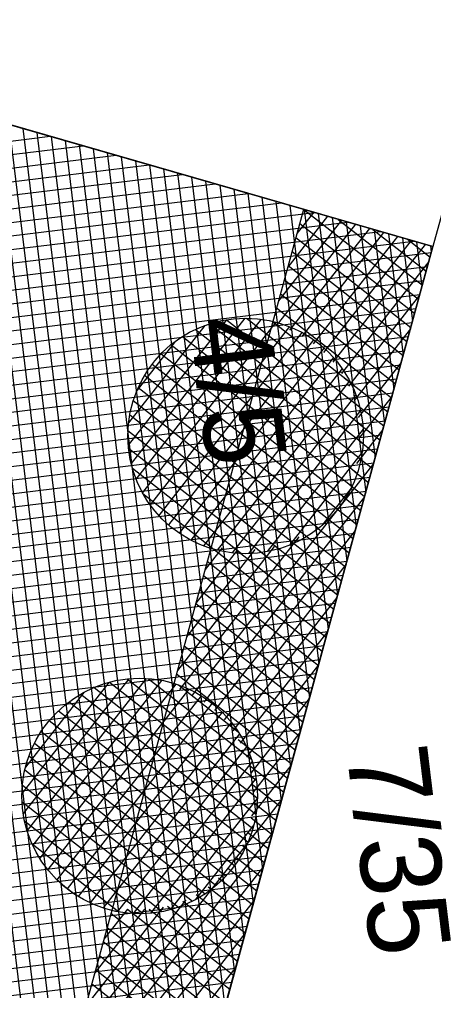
# Model space of a CAD drawing. Extents: x -566982 to -566809, y -1095912 to -1095685.
# Drawn here: x -566840.29 to -566834.14, y -1095771.74 to -1095757.31 of the extents above; entities that cross this region are included whole.
import ezdxf

# ---------------------------------------------------------------- set-up
doc = ezdxf.new("R2010")
doc.units = 0
for name, color, linetype in [('Vrstva 1', 7, 'Continuous'), ('Vrstva 40', 7, 'Continuous'), ('Vrstva 41', 7, 'Continuous'), ('Vrstva 42', 7, 'Continuous'), ('Vrstva 43', 7, 'Continuous'), ('Vrstva 44', 7, 'Continuous')]:
    doc.layers.add(name, color=color, linetype=linetype)

msp = doc.modelspace()

# ---------------------------------------------------------------- linework, layer by layer
at = {"layer": 'Vrstva 1'}
for p, q in [((-566831.34, -1095750.42), (-566834.15, -1095760.69)), ((-566843.76, -1095757.92), (-566834.15, -1095760.69)), ((-566834.15, -1095760.69), (-566839.47, -1095780.13))]:
    msp.add_line(p, q, dxfattribs=at)
at = {"layer": 'Vrstva 41'}
for p, q in [((-566835.922, -1095760.179), (-566836.171, -1095760.496)), ((-566836.07, -1095760.136), (-566834.364, -1095761.472)), ((-566835.508, -1095760.299), (-566836.444, -1095761.494)), ((-566835.715, -1095760.239), (-566836.307, -1095760.995)), ((-566835.556, -1095760.285), (-566834.307, -1095761.263)), ((-566835.301, -1095760.358), (-566836.48, -1095761.865)), ((-566835.094, -1095760.418), (-566836.279, -1095761.933)), ((-566836.129, -1095760.344), (-566834.421, -1095761.681)), ((-566835.043, -1095760.433), (-566834.249, -1095761.053)), ((-566836.186, -1095760.554), (-566834.478, -1095761.89)), ((-566834.886, -1095760.478), (-566836.096, -1095762.023)), ((-566834.679, -1095760.537), (-566835.928, -1095762.133)), ((-566834.472, -1095760.597), (-566835.774, -1095762.261)), ((-566834.529, -1095760.581), (-566834.192, -1095760.844)), ((-566836.244, -1095760.763), (-566834.536, -1095762.099)), ((-566834.265, -1095760.657), (-566835.635, -1095762.408)), ((-566836.301, -1095760.972), (-566834.593, -1095762.308)), ((-566834.211, -1095760.913), (-566835.511, -1095762.575)), ((-566836.358, -1095761.181), (-566834.65, -1095762.518)), ((-566836.415, -1095761.39), (-566834.707, -1095762.727)), ((-566834.348, -1095761.412), (-566835.404, -1095762.762)), ((-566836.472, -1095761.599), (-566834.765, -1095762.936)), ((-566836.53, -1095761.809), (-566836.447, -1095761.873)), ((-566834.484, -1095761.911), (-566835.318, -1095762.977)), ((-566834.621, -1095762.41), (-566835.259, -1095763.226)), ((-566835.47, -1095762.637), (-566834.822, -1095763.145)), ((-566834.757, -1095762.909), (-566835.236, -1095763.521)), ((-566835.306, -1095763.02), (-566834.879, -1095763.354)), ((-566835.245, -1095763.322), (-566834.936, -1095763.563)), ((-566834.894, -1095763.408), (-566835.287, -1095763.91)), ((-566835.238, -1095763.581), (-566834.994, -1095763.772)), ((-566835.03, -1095763.907), (-566837.727, -1095767.354)), ((-566835.264, -1095763.815), (-566835.051, -1095763.982)), ((-566835.319, -1095764.026), (-566835.108, -1095764.191)), ((-566835.396, -1095764.219), (-566835.165, -1095764.4)), ((-566835.167, -1095764.406), (-566837.554, -1095767.457)), ((-566835.493, -1095764.398), (-566835.223, -1095764.609)), ((-566835.608, -1095764.561), (-566835.28, -1095764.818)), ((-566835.742, -1095764.71), (-566835.337, -1095765.027)), ((-566835.304, -1095764.905), (-566837.395, -1095767.579)), ((-566835.895, -1095764.845), (-566835.394, -1095765.237)), ((-566836.141, -1095765.002), (-566837.916, -1095767.27)), ((-566836.266, -1095765.062), (-566835.509, -1095765.655)), ((-566836.068, -1095764.963), (-566835.451, -1095765.446)), ((-566836.507, -1095765.145), (-566837.946, -1095766.984)), ((-566836.795, -1095765.189), (-566837.81, -1095766.485)), ((-566837.053, -1095765.193), (-566837.673, -1095765.986)), ((-566837.283, -1095765.163), (-566837.536, -1095765.487)), ((-566837.446, -1095765.155), (-566835.738, -1095766.492)), ((-566837.072, -1095765.194), (-566835.68, -1095766.282)), ((-566836.754, -1095765.188), (-566835.623, -1095766.073)), ((-566836.491, -1095765.14), (-566835.566, -1095765.864)), ((-566837.503, -1095765.364), (-566835.795, -1095766.701)), ((-566835.44, -1095765.405), (-566837.253, -1095767.721)), ((-566837.56, -1095765.574), (-566835.852, -1095766.91)), ((-566837.617, -1095765.783), (-566835.909, -1095767.119)), ((-566835.577, -1095765.904), (-566837.125, -1095767.882)), ((-566837.675, -1095765.992), (-566835.967, -1095767.328)), ((-566837.732, -1095766.201), (-566836.024, -1095767.537)), ((-566837.789, -1095766.41), (-566836.081, -1095767.747)), ((-566835.713, -1095766.403), (-566837.014, -1095768.065)), ((-566837.846, -1095766.619), (-566836.138, -1095767.956)), ((-566837.903, -1095766.829), (-566836.196, -1095768.165)), ((-566835.85, -1095766.902), (-566836.922, -1095768.271)), ((-566837.961, -1095767.038), (-566836.253, -1095768.374)), ((-566835.987, -1095767.401), (-566836.854, -1095768.51)), ((-566836.123, -1095767.9), (-566836.82, -1095768.791)), ((-566837.044, -1095768.009), (-566836.31, -1095768.583)), ((-566836.885, -1095768.387), (-566836.367, -1095768.792)), ((-566836.26, -1095768.399), (-566836.845, -1095769.147)), ((-566836.827, -1095768.686), (-566836.425, -1095769.002)), ((-566836.396, -1095768.898), (-566839.476, -1095772.835)), ((-566836.822, -1095768.944), (-566836.482, -1095769.211)), ((-566836.849, -1095769.177), (-566836.539, -1095769.42)), ((-566836.533, -1095769.397), (-566839.272, -1095772.897)), ((-566836.907, -1095769.386), (-566836.596, -1095769.629)), ((-566836.985, -1095769.579), (-566836.654, -1095769.838)), ((-566837.083, -1095769.756), (-566836.711, -1095770.047)), ((-566836.669, -1095769.896), (-566839.083, -1095772.981)), ((-566837.2, -1095769.919), (-566836.768, -1095770.257)), ((-566837.335, -1095770.067), (-566836.825, -1095770.466)), ((-566837.489, -1095770.2), (-566836.882, -1095770.675)), ((-566837.82, -1095770.393), (-566839.448, -1095772.474)), ((-566836.806, -1095770.396), (-566838.91, -1095773.084)), ((-566837.867, -1095770.412), (-566836.997, -1095771.093)), ((-566837.666, -1095770.315), (-566836.94, -1095770.884)), ((-566838.16, -1095770.504), (-566839.312, -1095771.975)), ((-566838.436, -1095770.531), (-566839.175, -1095771.476)), ((-566838.689, -1095770.53), (-566839.039, -1095770.977)), ((-566838.69, -1095770.53), (-566837.169, -1095771.721)), ((-566838.366, -1095770.53), (-566837.111, -1095771.511)), ((-566838.095, -1095770.488), (-566837.054, -1095771.302)), ((-566838.934, -1095770.593), (-566837.226, -1095771.93)), ((-566838.991, -1095770.803), (-566837.283, -1095772.139)), ((-566836.943, -1095770.895), (-566838.751, -1095773.206)), ((-566839.048, -1095771.012), (-566837.34, -1095772.348)), ((-566839.105, -1095771.221), (-566837.398, -1095772.557)), ((-566839.163, -1095771.43), (-566837.455, -1095772.766)), ((-566837.079, -1095771.394), (-566838.609, -1095773.349)), ((-566839.22, -1095771.639), (-566837.512, -1095772.976))]:
    msp.add_line(p, q, dxfattribs=at)
at = {"layer": 'Vrstva 42'}
msp.add_lwpolyline([(-566834.15, -1095760.69), (-566836.072, -1095760.136), (-566841.286, -1095779.189), (-566855.268, -1095796.126), (-566881.984, -1095814.851), (-566891.818, -1095824.318), (-566954.342, -1095716.292), (-566956.66, -1095716.28), (-566892.27, -1095827.53), (-566880.71, -1095816.4), (-566853.9, -1095797.61), (-566839.47, -1095780.13)], close=True, dxfattribs=at)
at = {"layer": 'Vrstva 43'}
for p, q in [((-566841.913, -1095758.453), (-566839.33, -1095779.617)), ((-566841.704, -1095758.513), (-566839.19, -1095779.108)), ((-566841.495, -1095758.573), (-566839.051, -1095778.599)), ((-566841.286, -1095758.633), (-566838.912, -1095778.09)), ((-566841.077, -1095758.693), (-566838.772, -1095777.581)), ((-566840.868, -1095758.753), (-566838.633, -1095777.072)), ((-566840.66, -1095758.814), (-566838.494, -1095776.562)), ((-566840.451, -1095758.874), (-566838.354, -1095776.053)), ((-566840.242, -1095758.934), (-566838.215, -1095775.544)), ((-566840.033, -1095758.994), (-566838.076, -1095775.035)), ((-566844.216, -1095759.584), (-566839.839, -1095759.05)), ((-566839.824, -1095759.054), (-566837.936, -1095774.526)), ((-566839.615, -1095759.115), (-566837.797, -1095774.016)), ((-566839.407, -1095759.175), (-566837.658, -1095773.507)), ((-566844.273, -1095759.793), (-566839.348, -1095759.192)), ((-566839.198, -1095759.235), (-566837.518, -1095772.998)), ((-566838.989, -1095759.295), (-566837.379, -1095772.489)), ((-566844.33, -1095760.001), (-566838.857, -1095759.333)), ((-566838.78, -1095759.355), (-566837.24, -1095771.98)), ((-566838.571, -1095759.416), (-566837.1, -1095771.47)), ((-566844.387, -1095760.21), (-566838.366, -1095759.475)), ((-566838.362, -1095759.476), (-566836.961, -1095770.961)), ((-566838.154, -1095759.536), (-566836.822, -1095770.452)), ((-566837.945, -1095759.596), (-566836.682, -1095769.943)), ((-566844.444, -1095760.418), (-566837.875, -1095759.616)), ((-566837.736, -1095759.656), (-566836.543, -1095769.434)), ((-566837.527, -1095759.717), (-566836.403, -1095768.924)), ((-566844.558, -1095760.835), (-566836.893, -1095759.899)), ((-566844.501, -1095760.626), (-566837.384, -1095759.758)), ((-566837.318, -1095759.777), (-566836.264, -1095768.415)), ((-566837.109, -1095759.837), (-566836.125, -1095767.906)), ((-566836.901, -1095759.897), (-566835.985, -1095767.397)), ((-566844.615, -1095761.043), (-566836.402, -1095760.041)), ((-566836.692, -1095759.957), (-566835.846, -1095766.888)), ((-566836.483, -1095760.018), (-566835.707, -1095766.379)), ((-566844.672, -1095761.252), (-566835.91, -1095760.183)), ((-566836.274, -1095760.078), (-566835.567, -1095765.869)), ((-566836.065, -1095760.138), (-566835.428, -1095765.36)), ((-566844.729, -1095761.46), (-566835.419, -1095760.324)), ((-566835.856, -1095760.198), (-566835.289, -1095764.851)), ((-566835.648, -1095760.258), (-566835.149, -1095764.342)), ((-566835.439, -1095760.319), (-566835.01, -1095763.833)), ((-566844.786, -1095761.669), (-566834.928, -1095760.466)), ((-566835.23, -1095760.379), (-566834.871, -1095763.323)), ((-566835.021, -1095760.439), (-566834.731, -1095762.814)), ((-566844.843, -1095761.877), (-566834.437, -1095760.607)), ((-566834.812, -1095760.499), (-566834.592, -1095762.305)), ((-566834.604, -1095760.559), (-566834.453, -1095761.796)), ((-566834.395, -1095760.619), (-566834.313, -1095761.287)), ((-566834.186, -1095760.68), (-566834.174, -1095760.777)), ((-566844.9, -1095762.086), (-566834.174, -1095760.777)), ((-566844.957, -1095762.294), (-566834.231, -1095760.985)), ((-566845.014, -1095762.502), (-566834.288, -1095761.193)), ((-566845.071, -1095762.711), (-566834.345, -1095761.402)), ((-566845.128, -1095762.919), (-566834.402, -1095761.61)), ((-566845.185, -1095763.128), (-566834.459, -1095761.819)), ((-566845.242, -1095763.336), (-566834.516, -1095762.027)), ((-566845.3, -1095763.545), (-566834.573, -1095762.236)), ((-566845.357, -1095763.753), (-566834.63, -1095762.444)), ((-566845.414, -1095763.962), (-566834.687, -1095762.653)), ((-566845.471, -1095764.17), (-566834.744, -1095762.861)), ((-566845.528, -1095764.378), (-566834.801, -1095763.069)), ((-566845.585, -1095764.587), (-566834.858, -1095763.278)), ((-566845.642, -1095764.795), (-566834.915, -1095763.486)), ((-566845.699, -1095765.004), (-566834.972, -1095763.695)), ((-566845.756, -1095765.212), (-566835.029, -1095763.903)), ((-566845.813, -1095765.421), (-566835.086, -1095764.112)), ((-566845.87, -1095765.629), (-566835.143, -1095764.32)), ((-566845.927, -1095765.838), (-566835.2, -1095764.529)), ((-566845.984, -1095766.046), (-566835.258, -1095764.737)), ((-566846.041, -1095766.254), (-566835.315, -1095764.945)), ((-566846.098, -1095766.463), (-566835.372, -1095765.154)), ((-566846.155, -1095766.671), (-566835.429, -1095765.362)), ((-566846.212, -1095766.88), (-566835.486, -1095765.571)), ((-566846.269, -1095767.088), (-566835.543, -1095765.779)), ((-566846.327, -1095767.297), (-566835.6, -1095765.988)), ((-566846.384, -1095767.505), (-566835.657, -1095766.196)), ((-566846.441, -1095767.714), (-566835.714, -1095766.405)), ((-566846.498, -1095767.922), (-566835.771, -1095766.613)), ((-566846.555, -1095768.13), (-566835.828, -1095766.821)), ((-566846.612, -1095768.339), (-566835.885, -1095767.03)), ((-566846.669, -1095768.547), (-566835.942, -1095767.238)), ((-566846.726, -1095768.756), (-566835.999, -1095767.447)), ((-566846.783, -1095768.964), (-566836.056, -1095767.655)), ((-566846.84, -1095769.173), (-566836.113, -1095767.864)), ((-566846.897, -1095769.381), (-566836.17, -1095768.072)), ((-566846.954, -1095769.59), (-566836.227, -1095768.281)), ((-566847.011, -1095769.798), (-566836.284, -1095768.489)), ((-566847.068, -1095770.006), (-566836.341, -1095768.697)), ((-566847.125, -1095770.215), (-566836.398, -1095768.906)), ((-566847.182, -1095770.423), (-566836.455, -1095769.114)), ((-566847.239, -1095770.632), (-566836.512, -1095769.323)), ((-566847.296, -1095770.84), (-566836.57, -1095769.531)), ((-566847.354, -1095771.049), (-566836.627, -1095769.74)), ((-566847.411, -1095771.257), (-566836.684, -1095769.948)), ((-566847.468, -1095771.466), (-566836.741, -1095770.157)), ((-566847.525, -1095771.674), (-566836.798, -1095770.365)), ((-566847.582, -1095771.882), (-566836.855, -1095770.573)), ((-566847.639, -1095772.091), (-566836.912, -1095770.782)), ((-566847.696, -1095772.299), (-566836.969, -1095770.99)), ((-566847.753, -1095772.508), (-566837.026, -1095771.199)), ((-566847.81, -1095772.716), (-566837.083, -1095771.407)), ((-566847.867, -1095772.925), (-566837.14, -1095771.616))]:
    msp.add_line(p, q, dxfattribs=at)
msp.add_lwpolyline([(-566834.15, -1095760.69), (-566843.76, -1095757.92), (-566848.55, -1095775.42), (-566860.75, -1095790.2), (-566887.09, -1095808.66), (-566890.01, -1095811.47), (-566945.07, -1095716.34), (-566956.66, -1095716.28), (-566892.27, -1095827.53), (-566880.71, -1095816.4), (-566853.9, -1095797.61), (-566839.47, -1095780.13)], close=True, dxfattribs=at)
at = {"layer": 'Vrstva 44'}
for p, q in [((-566837.218, -1095761.775), (-566838.677, -1095763.64)), ((-566836.946, -1095761.752), (-566838.635, -1095763.911)), ((-566836.704, -1095761.768), (-566838.561, -1095764.141)), ((-566837.216, -1095761.775), (-566835.192, -1095763.359)), ((-566836.922, -1095761.752), (-566835.241, -1095763.067)), ((-566837.538, -1095761.86), (-566838.672, -1095763.309)), ((-566836.485, -1095761.812), (-566838.466, -1095764.344)), ((-566836.283, -1095761.878), (-566838.353, -1095764.524)), ((-566837.464, -1095761.835), (-566835.188, -1095763.616)), ((-566836.538, -1095761.798), (-566835.377, -1095762.706)), ((-566836.097, -1095761.965), (-566838.223, -1095764.682)), ((-566837.872, -1095762.024), (-566835.276, -1095764.055)), ((-566837.68, -1095761.92), (-566835.22, -1095763.845)), ((-566837.978, -1095762.098), (-566838.545, -1095762.823)), ((-566835.927, -1095762.072), (-566838.079, -1095764.822)), ((-566838.04, -1095762.147), (-566835.353, -1095764.249)), ((-566835.77, -1095762.197), (-566837.92, -1095764.945)), ((-566838.189, -1095762.284), (-566835.45, -1095764.427)), ((-566835.628, -1095762.339), (-566837.748, -1095765.05)), ((-566838.32, -1095762.435), (-566835.566, -1095764.59)), ((-566838.434, -1095762.6), (-566835.7, -1095764.739)), ((-566835.5, -1095762.5), (-566837.561, -1095765.134)), ((-566838.528, -1095762.78), (-566835.852, -1095764.874)), ((-566835.389, -1095762.683), (-566837.357, -1095765.198)), ((-566835.297, -1095762.89), (-566837.135, -1095765.239)), ((-566838.602, -1095762.976), (-566836.023, -1095764.995)), ((-566838.655, -1095763.189), (-566836.218, -1095765.096)), ((-566835.226, -1095763.124), (-566836.888, -1095765.248)), ((-566838.682, -1095763.422), (-566836.438, -1095765.177)), ((-566835.189, -1095763.401), (-566836.612, -1095765.22)), ((-566838.673, -1095763.683), (-566836.692, -1095765.233)), ((-566835.203, -1095763.744), (-566836.282, -1095765.123)), ((-566838.615, -1095763.982), (-566836.995, -1095765.249)), ((-566838.46, -1095764.357), (-566837.399, -1095765.187)), ((-566835.367, -1095764.278), (-566835.8, -1095764.831)), ((-566838.67, -1095767.109), (-566840.237, -1095769.112)), ((-566838.413, -1095767.106), (-566840.179, -1095769.363)), ((-566838.693, -1095767.112), (-566836.775, -1095768.613)), ((-566838.374, -1095767.108), (-566836.846, -1095768.304)), ((-566838.966, -1095767.163), (-566840.256, -1095768.811)), ((-566838.181, -1095767.133), (-566840.097, -1095769.582)), ((-566837.969, -1095767.187), (-566839.993, -1095769.773)), ((-566839.182, -1095767.238), (-566836.779, -1095769.118)), ((-566838.956, -1095767.16), (-566836.76, -1095768.879)), ((-566837.931, -1095767.201), (-566837.044, -1095767.895)), ((-566839.336, -1095767.311), (-566840.204, -1095768.421)), ((-566837.775, -1095767.264), (-566839.872, -1095769.944)), ((-566837.596, -1095767.36), (-566839.737, -1095770.095)), ((-566839.38, -1095767.336), (-566836.827, -1095769.334)), ((-566837.431, -1095767.473), (-566839.587, -1095770.228)), ((-566839.557, -1095767.452), (-566836.898, -1095769.533)), ((-566839.713, -1095767.584), (-566836.988, -1095769.716)), ((-566837.28, -1095767.604), (-566839.422, -1095770.342)), ((-566839.85, -1095767.731), (-566837.097, -1095769.885)), ((-566837.144, -1095767.756), (-566839.242, -1095770.437)), ((-566839.969, -1095767.892), (-566837.224, -1095770.039)), ((-566837.024, -1095767.927), (-566839.048, -1095770.514)), ((-566840.07, -1095768.066), (-566837.37, -1095770.179)), ((-566836.92, -1095768.119), (-566838.837, -1095770.568)), ((-566840.153, -1095768.255), (-566837.535, -1095770.304)), ((-566836.836, -1095768.336), (-566838.605, -1095770.597)), ((-566840.213, -1095768.463), (-566837.721, -1095770.413)), ((-566840.248, -1095768.689), (-566837.931, -1095770.502)), ((-566836.779, -1095768.588), (-566838.348, -1095770.592)), ((-566840.255, -1095768.937), (-566838.173, -1095770.567)), ((-566836.76, -1095768.888), (-566838.054, -1095770.541)), ((-566840.217, -1095769.221), (-566838.457, -1095770.598)), ((-566836.812, -1095769.278), (-566837.684, -1095770.393)), ((-566840.107, -1095769.561), (-566838.816, -1095770.572)), ((-566839.668, -1095770.159), (-566839.494, -1095770.295))]:
    msp.add_line(p, q, dxfattribs=at)
for centre in [(-566836.934, -1095763.501), (-566838.508, -1095768.851)]:
    msp.add_circle(centre, 1.75, dxfattribs=at)

# ---------------------------------------------------------------- texts
at = {"layer": 'Vrstva 40'}
for s, p in [('4/5', (-566837.769, -1095761.779)), ('7/35', (-566835.437, -1095768.174))]:
    msp.add_text(s, height=1.2, rotation=276.9575, dxfattribs=at).set_placement(p)

doc.saveas('drawing.dxf')
